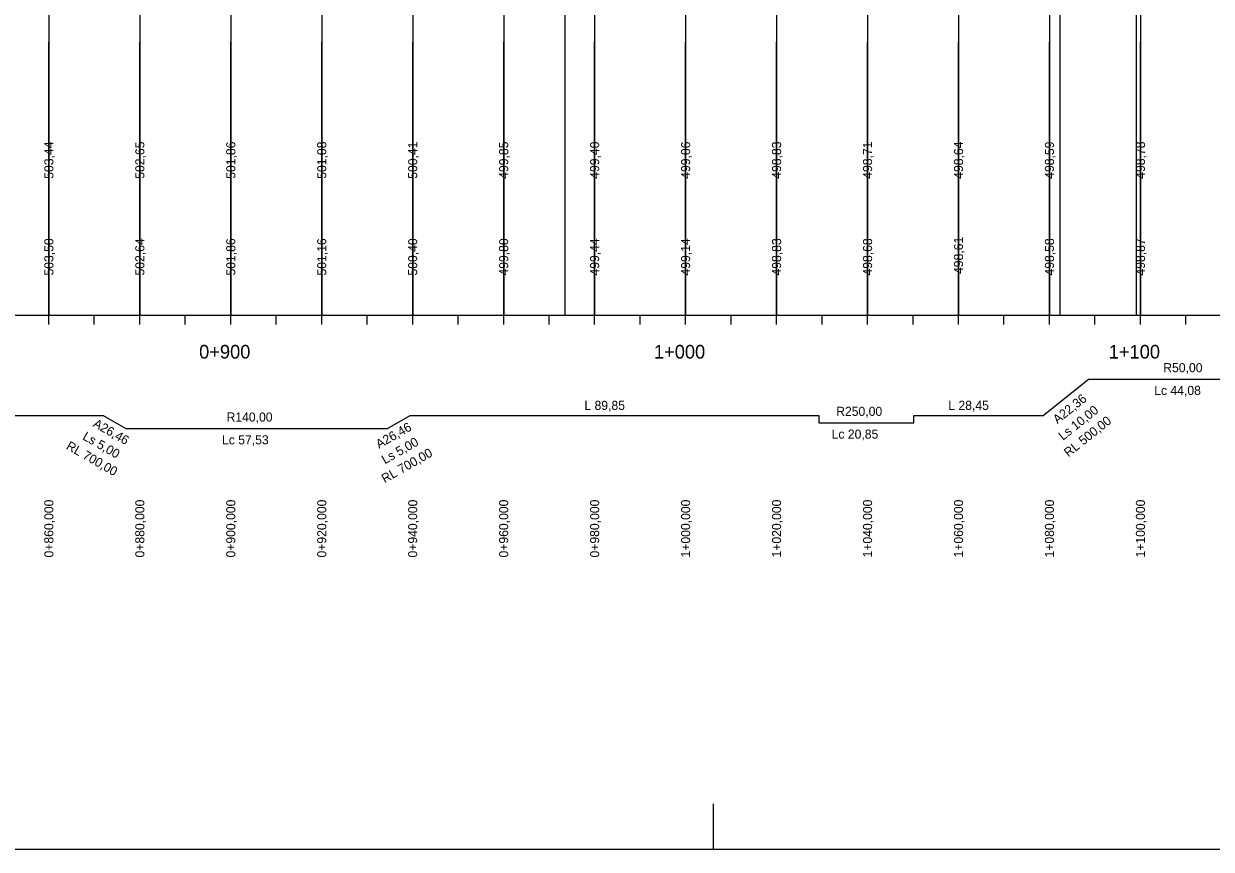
# Model space of a CAD drawing. Extents: x -632716 to -629545, y -1094726 to -1088285.
# Drawn here: x -631756.3 to -631495.2, y -1093689.1 to -1093507.7 of the extents above; entities that cross this region are included whole.
import ezdxf

# ---------------------------------------------------------------- set-up
doc = ezdxf.new("R2010")
doc.units = 0
for name, color, linetype in [('20', 7, 'Continuous'), ('formát', 7, 'Continuous'), ('NIVELETA_VYSKY', 7, 'Continuous'), ('REZ_POPIS', 7, 'Continuous'), ('REZ_TABULKA', 7, 'Continuous'), ('REZ_TENKA', 7, 'Continuous'), ('REZ_TLUSTA', 7, 'Continuous'), ('SKLONY_NIVELETA', 7, 'Continuous'), ('TEREN_VYSKY', 7, 'Continuous')]:
    doc.layers.add(name, color=color, linetype=linetype)

msp = doc.modelspace()

# ---------------------------------------------------------------- linework, layer by layer
at = {"layer": '20'}
for points in [[(-631750.75, -1093387.37), (-631750.75, -1093521.74), (-631750.75, -1093571.74), (-631750.75, -1093511.74)], [(-631730.75, -1093395.26), (-631730.75, -1093521.74), (-631730.75, -1093571.74), (-631730.75, -1093511.74)], [(-631710.75, -1093403.17), (-631710.75, -1093521.74), (-631710.75, -1093571.74), (-631710.75, -1093511.74)], [(-631690.75, -1093410.91), (-631690.75, -1093521.74), (-631690.75, -1093571.74), (-631690.75, -1093511.74)], [(-631670.75, -1093417.63), (-631670.75, -1093521.74), (-631670.75, -1093571.74), (-631670.75, -1093511.74)], [(-631650.75, -1093423.25), (-631650.75, -1093521.74), (-631650.75, -1093571.74), (-631650.75, -1093511.74)], [(-631630.75, -1093427.76), (-631630.75, -1093521.74), (-631630.75, -1093571.74), (-631630.75, -1093511.74)], [(-631610.75, -1093431.15), (-631610.75, -1093521.74), (-631610.75, -1093571.74), (-631610.75, -1093511.74)], [(-631590.75, -1093433.44), (-631590.75, -1093521.74), (-631590.75, -1093571.74), (-631590.75, -1093511.74)], [(-631510.75, -1093433.91), (-631510.75, -1093521.74), (-631510.75, -1093571.74), (-631510.75, -1093511.74)], [(-631570.75, -1093434.61), (-631570.75, -1093521.74), (-631570.75, -1093571.74), (-631570.75, -1093511.74)], [(-631550.75, -1093435.32), (-631550.75, -1093521.74), (-631550.75, -1093571.74), (-631550.75, -1093511.74)], [(-631530.75, -1093435.82), (-631530.75, -1093521.74), (-631530.75, -1093571.74), (-631530.75, -1093511.74)]]:
    msp.add_lwpolyline(points, dxfattribs=at)
at = {"layer": 'formát'}
msp.add_line((-631604.61, -1093689.05), (-631604.61, -1093679.05), dxfattribs=at)
msp.add_lwpolyline([(-632715.96, -1093689.05), (-630764.61, -1093689.05), (-630764.61, -1093095.05), (-632715.96, -1093095.05)], close=True, dxfattribs=at)
at = {"layer": 'REZ_TABULKA'}
msp.add_lwpolyline([(-631971.6, -1093593.74), (-631738.82, -1093593.74), (-631738.82, -1093593.74), (-631733.82, -1093596.59), (-631733.82, -1093596.59), (-631676.3, -1093596.59), (-631676.3, -1093596.59), (-631671.3, -1093593.74), (-631671.3, -1093593.74), (-631581.44, -1093593.74), (-631581.44, -1093595.34), (-631560.59, -1093595.34), (-631560.59, -1093593.74), (-631532.14, -1093593.74), (-631532.14, -1093593.74), (-631522.14, -1093585.74), (-631522.14, -1093585.74), (-631478.06, -1093585.74)], dxfattribs=at)
at = {"layer": 'REZ_TENKA'}
for p, q in [((-631750.75, -1093573.74), (-631750.75, -1093571.74)), ((-631740.75, -1093573.74), (-631740.75, -1093571.74)), ((-631730.75, -1093573.74), (-631730.75, -1093571.74)), ((-631720.75, -1093573.74), (-631720.75, -1093571.74)), ((-631700.75, -1093573.74), (-631700.75, -1093571.74)), ((-631690.75, -1093573.74), (-631690.75, -1093571.74)), ((-631680.75, -1093573.74), (-631680.75, -1093571.74)), ((-631670.75, -1093573.74), (-631670.75, -1093571.74)), ((-631660.75, -1093573.74), (-631660.75, -1093571.74)), ((-631650.75, -1093573.74), (-631650.75, -1093571.74)), ((-631640.75, -1093573.74), (-631640.75, -1093571.74)), ((-631630.75, -1093573.74), (-631630.75, -1093571.74)), ((-631620.75, -1093573.74), (-631620.75, -1093571.74)), ((-631600.75, -1093573.74), (-631600.75, -1093571.74)), ((-631590.75, -1093573.74), (-631590.75, -1093571.74)), ((-631580.75, -1093573.74), (-631580.75, -1093571.74)), ((-631570.75, -1093573.74), (-631570.75, -1093571.74)), ((-631560.75, -1093573.74), (-631560.75, -1093571.74)), ((-631550.75, -1093573.74), (-631550.75, -1093571.74)), ((-631540.75, -1093573.74), (-631540.75, -1093571.74)), ((-631530.75, -1093573.74), (-631530.75, -1093571.74)), ((-631520.75, -1093573.74), (-631520.75, -1093571.74)), ((-631500.75, -1093573.74), (-631500.75, -1093571.74))]:
    msp.add_line(p, q, dxfattribs=at)
at = {"layer": 'REZ_TLUSTA'}
for p, q in [((-631710.75, -1093573.74), (-631710.75, -1093569.74)), ((-631610.75, -1093573.74), (-631610.75, -1093569.74)), ((-631510.75, -1093573.74), (-631510.75, -1093569.74)), ((-632610.75, -1093571.74), (-631190.75, -1093571.74))]:
    msp.add_line(p, q, dxfattribs=at)
at = {"layer": 'SKLONY_NIVELETA'}
for p, q in [((-631637.27, -1093332.25), (-631637.27, -1093571.74)), ((-631511.71, -1093333.11), (-631511.71, -1093571.74)), ((-631528.45, -1093336.11), (-631528.45, -1093571.74))]:
    msp.add_line(p, q, dxfattribs=at)

# ---------------------------------------------------------------- texts
at = {"layer": 'NIVELETA_VYSKY'}
for s, p in [('503,44', (-631749.75, -1093541.74)), ('502,65', (-631729.75, -1093541.74)), ('501,86', (-631709.75, -1093541.74)), ('501,08', (-631689.75, -1093541.74)), ('500,41', (-631669.75, -1093541.74)), ('499,85', (-631649.75, -1093541.74)), ('499,40', (-631629.75, -1093541.74)), ('499,06', (-631609.75, -1093541.74)), ('498,83', (-631589.75, -1093541.74)), ('498,71', (-631569.75, -1093541.74)), ('498,64', (-631549.75, -1093541.74)), ('498,59', (-631529.75, -1093541.74)), ('498,78', (-631509.75, -1093541.74))]:
    msp.add_text(s, height=2, rotation=90, dxfattribs=at).set_placement(p)
at = {"layer": 'REZ_POPIS'}
for s, p in [('0+900', (-631717.71, -1093581.24)), ('1+000', (-631617.71, -1093581.24)), ('1+100', (-631517.71, -1093581.24))]:
    msp.add_text(s, height=3, dxfattribs=at).set_placement(p)
at = {"layer": 'REZ_TABULKA'}
for s, p in [('R50,00', (-631505.73, -1093584.24)), ('Lc 44,08', (-631507.72, -1093589.24)), ('L 89,85', (-631633, -1093592.52)), ('L 28,45', (-631552.99, -1093592.52)), ('R140,00', (-631711.68, -1093595.09)), ('R250,00', (-631577.64, -1093593.84)), ('Lc 57,53', (-631712.68, -1093600.09)), ('Lc 20,85', (-631578.64, -1093598.84))]:
    msp.add_text(s, height=2, dxfattribs=at).set_placement(p)
for s, rotation, p in [('A22,36', 38.6598, (-631529, -1093595.69)), ('Ls 10,00', 38.6598, (-631527.79, -1093599.34)), ('A26,46', 330.2551, (-631741.22, -1093596.08)), ('A26,46', 29.7449, (-631678.16, -1093601.09)), ('RL 500,00', 38.6598, (-631526.58, -1093602.98)), ('Ls 5,00', 330.2551, (-631743.5, -1093598.92)), ('Ls 5,00', 29.7449, (-631676.87, -1093604.5)), ('RL 700,00', 330.2551, (-631747.11, -1093601.01)), ('RL 700,00', 29.7449, (-631676.9, -1093608.67)), ('0+860,000', 90, (-631749.75, -1093624.95)), ('0+880,000', 90, (-631729.75, -1093624.95)), ('0+900,000', 90, (-631709.75, -1093624.95)), ('0+920,000', 90, (-631689.75, -1093624.95)), ('0+940,000', 90, (-631669.75, -1093624.95)), ('0+960,000', 90, (-631649.75, -1093624.95)), ('0+980,000', 90, (-631629.75, -1093624.95)), ('1+000,000', 90, (-631609.75, -1093624.95)), ('1+020,000', 90, (-631589.75, -1093624.95)), ('1+040,000', 90, (-631569.75, -1093624.95)), ('1+060,000', 90, (-631549.75, -1093624.95)), ('1+080,000', 90, (-631529.75, -1093624.95)), ('1+100,000', 90, (-631509.75, -1093624.95))]:
    msp.add_text(s, height=2, rotation=rotation, dxfattribs=at).set_placement(p)
at = {"layer": 'TEREN_VYSKY'}
for s, p in [('503,50', (-631749.75, -1093563)), ('502,64', (-631729.75, -1093563)), ('501,86', (-631709.75, -1093563)), ('501,16', (-631689.75, -1093563)), ('500,40', (-631669.75, -1093563)), ('499,80', (-631649.75, -1093563)), ('499,44', (-631629.75, -1093563)), ('499,14', (-631609.75, -1093563)), ('498,83', (-631589.75, -1093563)), ('498,68', (-631569.75, -1093563)), ('498,61', (-631549.75, -1093562.66)), ('498,58', (-631529.75, -1093563)), ('498,87', (-631509.75, -1093563))]:
    msp.add_text(s, height=2, rotation=90, dxfattribs=at).set_placement(p)

doc.saveas('drawing.dxf')
